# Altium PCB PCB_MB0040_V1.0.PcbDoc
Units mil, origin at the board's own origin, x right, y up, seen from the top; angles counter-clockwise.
Board outline 2760.94 x 3491.25 mil, 2 copper layers (Top Layer, Bottom Layer), stack 21 mil thick; 52 components, 72 nets, 310 pads, 64 vias.
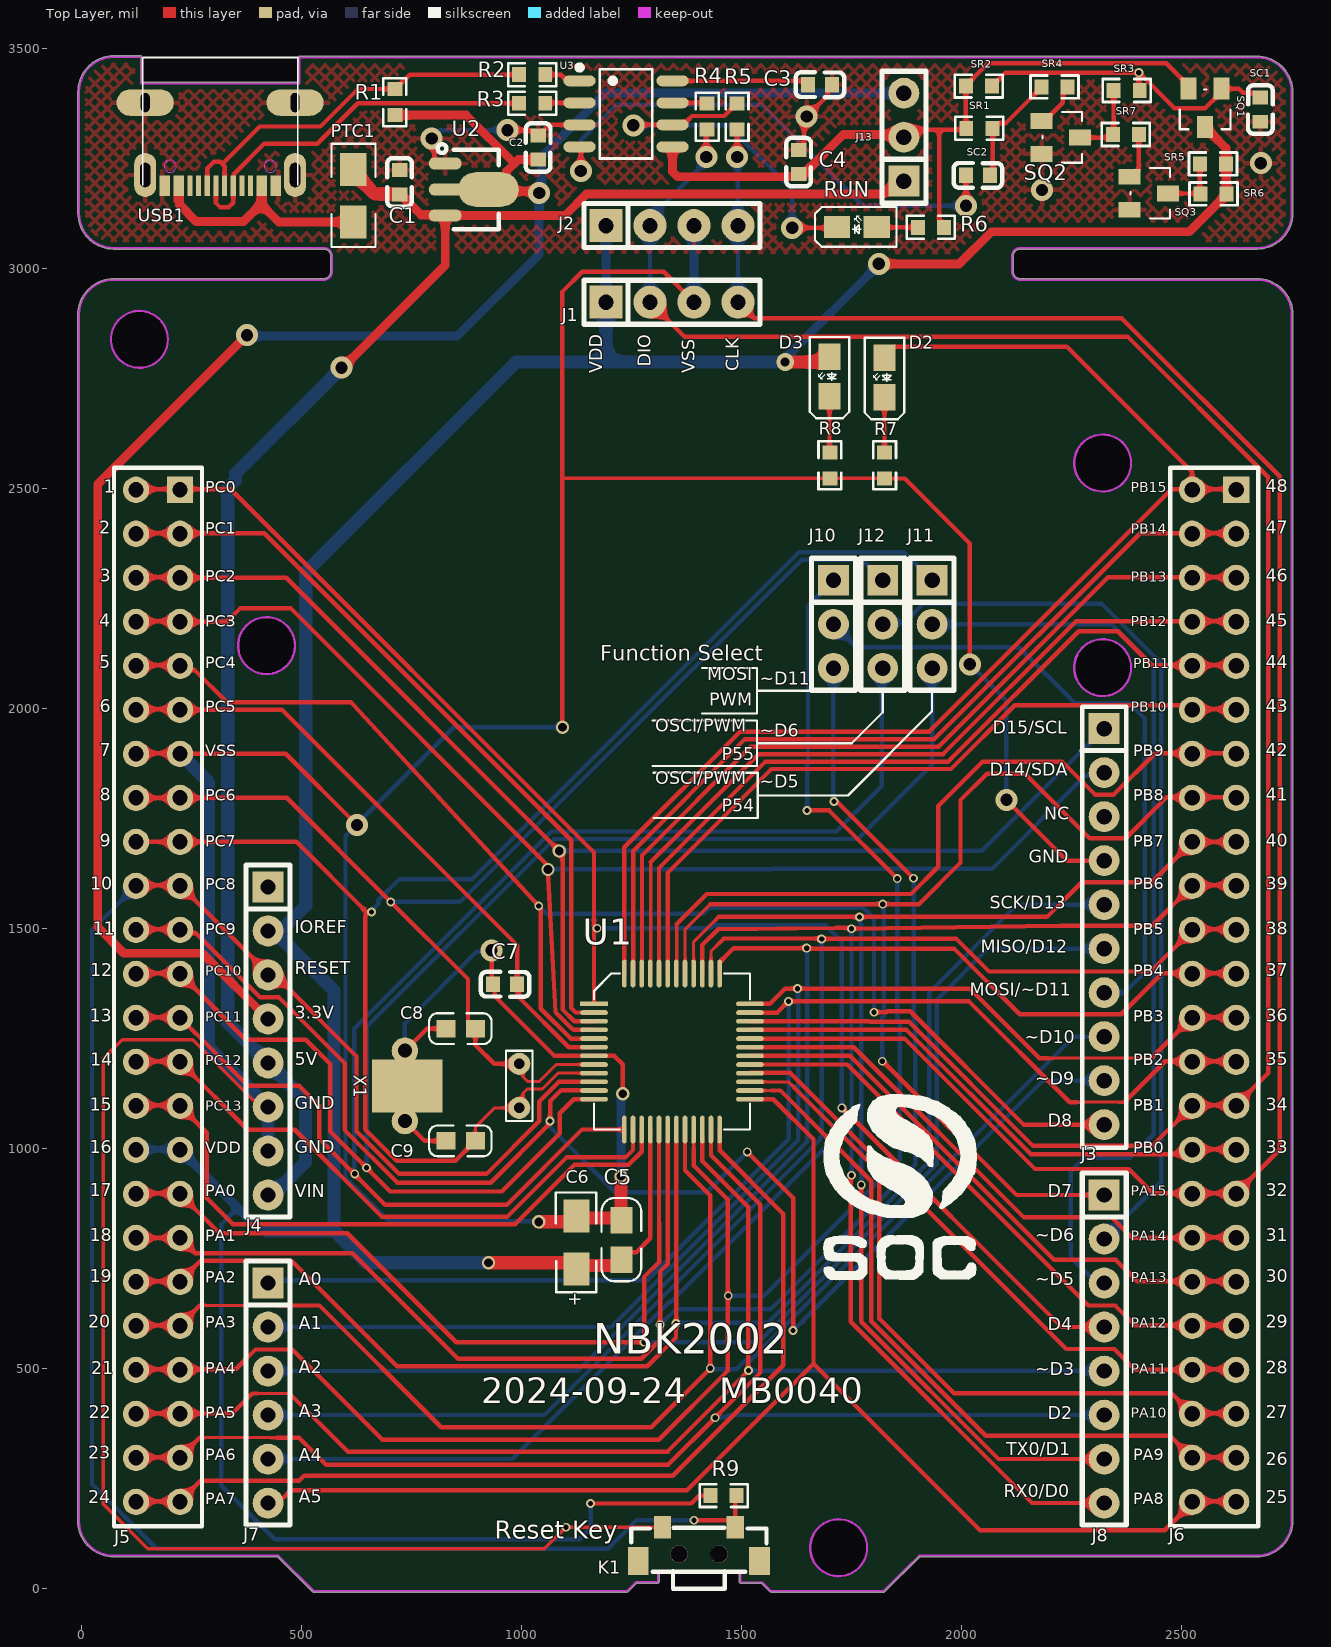
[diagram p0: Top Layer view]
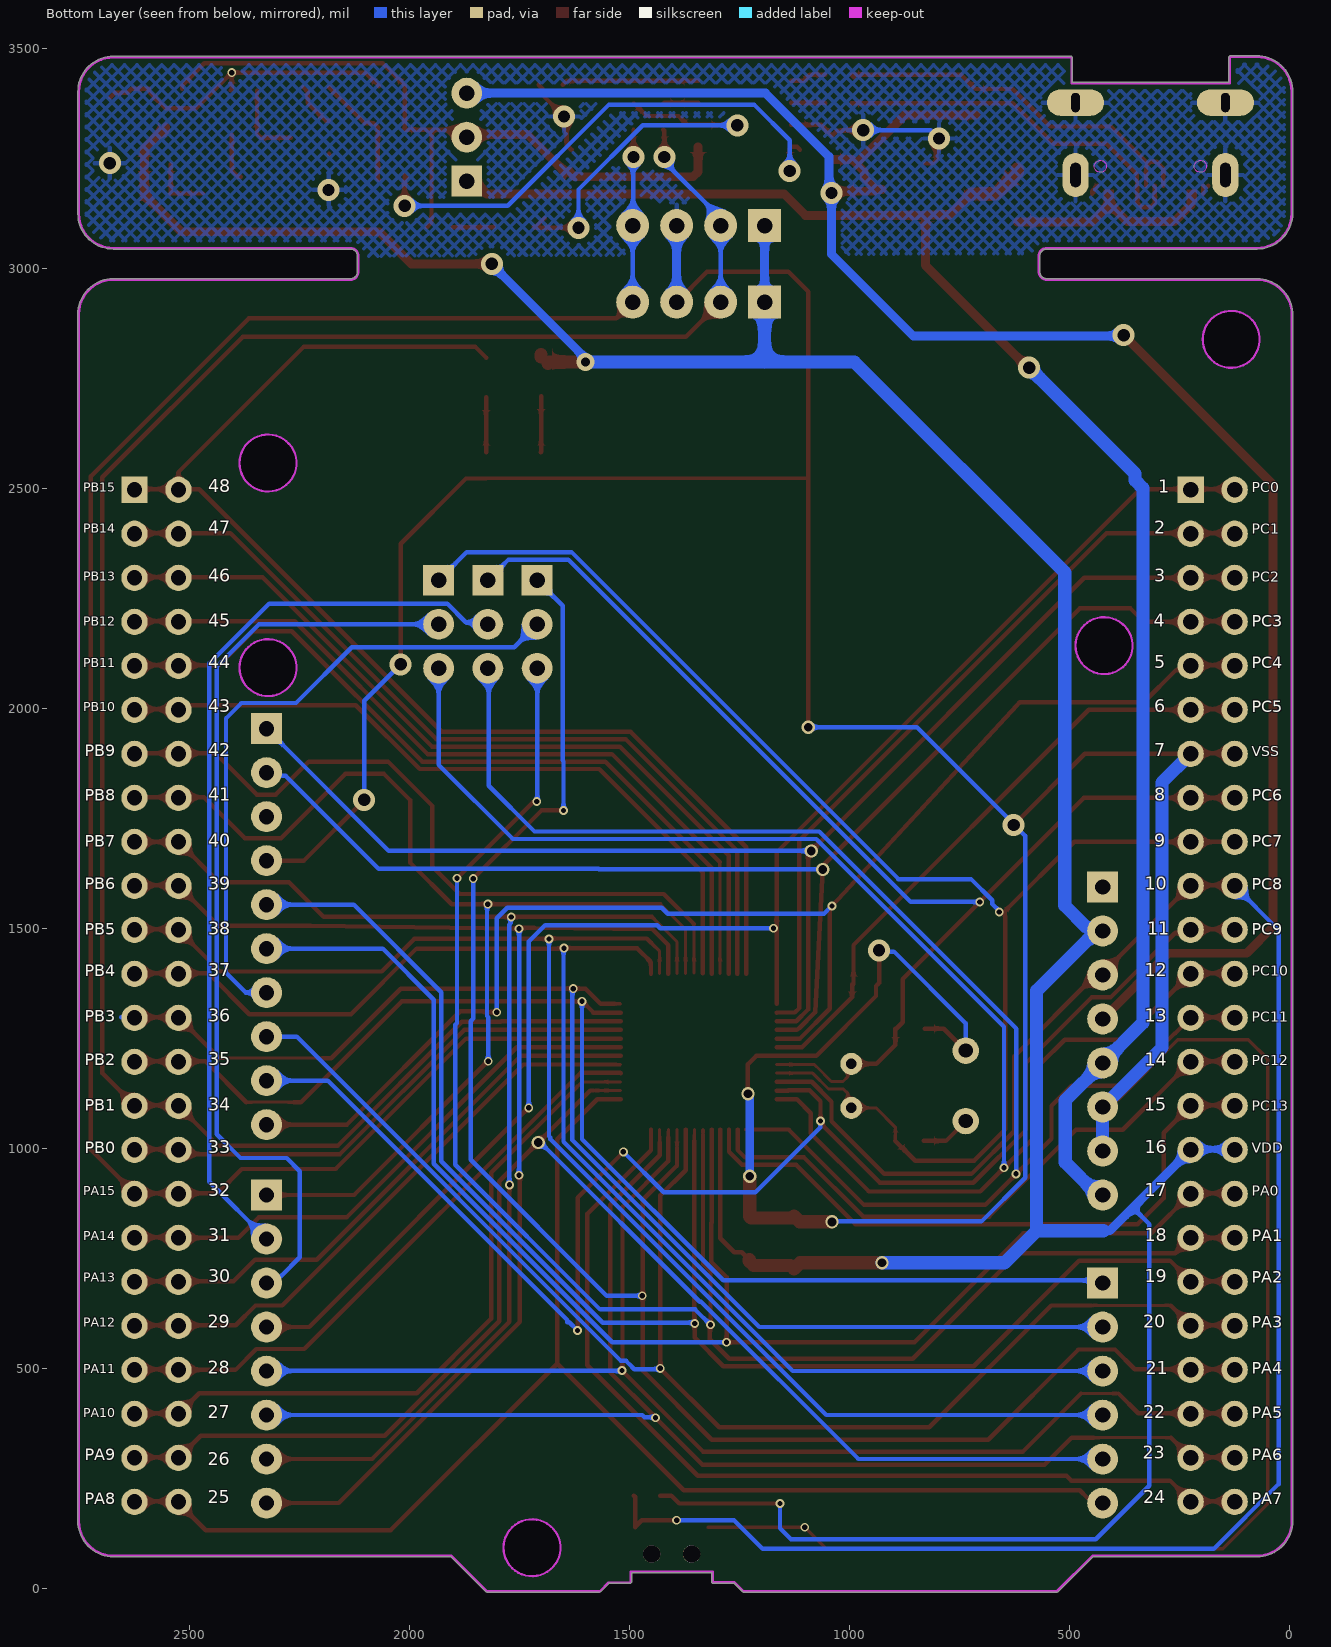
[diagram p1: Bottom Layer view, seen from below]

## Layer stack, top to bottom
Top Solder: solder mask 0.4, Solder Resist, Dk 3.5
Top Layer: signal copper 1.4
Dielectric 1: prepreg 2.8, PP-006, Dk 4.1
Dielectric1: dielectric 12.6, FR-4, Dk 4.8
Dielectric 2: prepreg 2.8, PP-006, Dk 4.1
Bottom Layer: signal copper 1.4
Bottom Solder: solder mask 0.4, Solder Resist, Dk 3.5

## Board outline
73.06,71.8 446.03,71.8 525.62,-7.79 527.39,-8.52 1240.4,-8.52 1242.18,-7.78 1261.44,11.48 1310,11.48 1312.51,14 1312.51,35.49 1494.49,35.49 1494.49,13.73 1497.36,11.21 1545.92,11.21 1565.18,-8.05 1568.1,-8.52 1823.45,-8.52 1825.23,-7.78 1904.81,71.8 2671.48,71.8 ccw(c2671.48,153.06) 2752.74,153.05 2752.74,2895.58 ccw(c2672.03,2895.58) 2672.58,2976.28 2671.95,2976.37 2133.15,2976.37 cw(c2133.15,2992) 2117.51,2992 2117.51,3028 cw(c2133.15,3028) 2133.15,3043.63 2671.95,3043.63 ccw(c2671.95,3124.34) 2752.66,3124.34 2752.66,3400.93 ccw(c2671.95,3400.93) 2671.95,3481.64 495,3481.64 492.49,3479.12 492.49,3422.52 137.51,3422.52 137.51,3480 134.78,3482.74 73.35,3482.74 ccw(c73.35,3401.48) -7.91,3401.48 -7.91,3124.89 ccw(c73.35,3124.89) 73.22,3043.63 550.95,3043.63 cw(c550.95,3028) 566.59,3028 566.59,2992 cw(c550.95,2992) 550.95,2976.37 550.06,2976.2 73.06,2976.2 ccw(c73.05,2894.94) -8.03,2900.23 -8.2,2899.31 -8.2,154 -8.2,153.05 ccw(c73.06,153.05)
cut-out: 1655.98,92.43 ccw(c1720.69,92.43) 1720.69,27.71 ccw(c1720.69,92.43) 1785.41,92.43 ccw(c1720.69,92.43) 1720.69,157.14 ccw(c1720.69,92.43)
cut-out: 2255.98,2092.43 ccw(c2320.69,2092.43) 2320.69,2027.71 ccw(c2320.69,2092.43) 2385.41,2092.43 ccw(c2320.69,2092.43) 2320.69,2157.14 ccw(c2320.69,2092.43)
cut-out: 355.98,2142.43 ccw(c420.69,2142.43) 420.69,2077.71 ccw(c420.69,2142.43) 485.41,2142.43 ccw(c420.69,2142.43) 420.69,2207.14 ccw(c420.69,2142.43)
cut-out: 2255.98,2557.43 ccw(c2320.69,2557.43) 2320.69,2492.71 ccw(c2320.69,2557.43) 2385.41,2557.43 ccw(c2320.69,2557.43) 2320.69,2622.14 ccw(c2320.69,2557.43)
cut-out: 66.98,2838.43 ccw(c131.69,2838.43) 131.69,2773.71 ccw(c131.69,2838.43) 196.41,2838.43 ccw(c131.69,2838.43) 131.69,2903.14 ccw(c131.69,2838.43)

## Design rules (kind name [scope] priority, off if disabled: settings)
Clearance [InNamedPolygon('GND_L01_P001')] p1: gap=10 ignorepadtopadclearanceinfootprint=FALSE
Clearance Clearance_2 [(InComponent('U1') AND IsPad)] p2: gap=6 ignorepadtopadclearanceinfootprint=FALSE except(0: Arc-Hole Track-Hole SMDPad-Hole THPad-Hole Via-Hole Fill-Hole Poly-Hole Region-Hole Text-Hole)
Clearance Clearance_1 [All] p3: gap=6 ignorepadtopadclearanceinfootprint=FALSE except(0: Arc-Hole Track-Hole SMDPad-Hole THPad-Hole Via-Hole Fill-Hole Poly-Hole Region-Hole Text-Hole)
ComponentClearance [All] p1 off: gap=10 collisioncheckmode=3 verticalgap=10 showdistances=FALSE
Height [All] p1 off: minheight=0 maxheight=1000 prefheight=500
HoleSize [All] p1: absolutevalues=TRUE maxlimit=150 minlimit=1 maxpercent=80.000 minpercent=20.000
MinimumSolderMaskSliver [All] p1: minsoldermaskwidth=0
PolygonConnect [All] p1: connectstyle=Relief reliefconductorwidth=10 reliefentries=4 polygonreliefangle="90 Angle" airgapwidth=10
RoutingVias [All] p1: holewidth=28 width=50 viastyle="Through Hole" minholewidth=10 minwidth=20 maxholewidth=130 maxwidth=180
SilkToSilkClearance [All] p1 off: silktosilkclearance=0
SilkToSolderMaskClearance [IsPad] p1 off: minsilkscreentomaskgap=0 clearancetoexposedcopper=TRUE
SolderMaskExpansion [All] p1: expansion=4 istentingtop=FALSE
Width [All] p1: maxlimit=30 minlimit=5 preferedwidth=7
24 further rules are at their usual default settings.

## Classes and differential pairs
component class SCH_MB0040: C1 C2 C3 C4 C5 C6 C7 C8 C9 D2 D3 J1 J2 J3 J4 J5 J6 J7 J8 J10 J11 J12 J13 K1 PTC1 R1 R2 R3 R4 R5 R6 R7 R8 R9 RUN SC1 SC2 SQ1 SQ2 SR1 SR2 SR3 SR4 SR5 SR6 SR7 U1 USB1 X1

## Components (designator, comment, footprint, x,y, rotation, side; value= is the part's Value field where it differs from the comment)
C1 "104" C0603#1 723,3195.56 r90 top
C2 "104" C0603#1 1038,3274.56 r90 top
C3 "104" C0603#1 1678.44,3417 r0 top
C4 "104" C0603#1 1630,3241.56 r90 top
C5 "104" C0805 1227,747 r90 top
C6 "10uF" A-3216 1125,726 r90 top
C7 "103" C0603#1 962.44,1373 r180 top
C8 "10pF" C0603#2 895,1272 r180 top
C9 "10pF" C0603#2 895,1017 r180 top
D2 "LED-Bule" LED0805 1825,2752 r270 top
D3 "LED-Yellow" LED0805 1700,2754 r270 top
J1 "CON1*4" CON1*4(P=2.54) 1342,2923 r0 top locked
J2 "CON1*4" CON1*4(P=2.54) 1342,3097 r0 top locked
J3 "CON1*10" CON1*10(P=2.54) 2324,1504 r270 top locked
J4 "CON1*8" CON1*8(P=2.54) 424,1244 r270 top locked
J5 "CON2*24" CON2*24(P=2.54) 189,1346.5 r270 top locked
J6 "CON2*24" CON2*24(P=2.54) 2589,1346.5 r270 top locked
J7 "CON1*6" CON1*6(P=2.54) 424,444 r270 top locked
J8 "CON1*8" CON1*8(P=2.54) 2324,544 r270 top locked
J10 "CON1*3" CON1*3(P=2.54) 1709,2191 r270 top locked
J11 "CON1*3" CON1*3(P=2.54) 1933,2191 r270 top locked
J12 "CON1*3" CON1*3(P=2.54) 1821,2191 r270 top locked
J13 "Header 4" CON1*3(P=2.54) 1869,3298 r90 top
K1 "单路开关" SW-SMD_UK-B0246-SP25Y 1403.28,100.64 r180 top
PTC1 "0.5A 6V 自恢复保险丝" R1206 618,3105 r90 top
R1 "1.5K" R0603 712,3377.66 r90 top
R2 "22R" R0603 1024.34,3440 r0 top
R3 "22R" R0603 1024.34,3375 r0 top
R4 "100R" R0603 1422,3344.66 r90 top
R5 "100R" R0603 1490,3344.66 r90 top
R6 "2.2K" R0603 1930.34,3093 r180 top
R7 "5.1K" R0603 1825,2552 r270 top
R8 "5.1K" R0603 1701,2552 r270 top
R9 "1.5K" R0603 1459.34,211 r180 top
RUN "LED-Bule" LED0805 1762,3094 r180 top (schematic designator D1)
SC1 "104" C0603#1 2679,3360.56 r270 top
SC2 "Cap" C0603#1 2037.44,3211 r0 top value=22uF
SQ1 "SI2301" sanjiguan 2516,3408 r270 top
SQ2 "SI2302" sanjiguan 2182,3260 r0 top
SQ3 "SI2302" sanjiguan 2382,3133 r0 top
SR1 "47K" R0603 2040.34,3318 r180 top
SR2 "47K" R0603 2039.34,3414 r0 top
SR3 "4.7K" R0603 2375.34,3404 r0 top
SR4 "47k" R0603 2211.34,3412 r180 top
SR5 "22R" R0603 2571.34,3237 r0 top
SR6 "22R" R0603 2572.66,3169 r0 top
SR7 "4.7K" R0603 2373.34,3304 r180 top
U1 "SC32F12TC9" CH48 1162,1045 r0 top locked
U2 "AMS1117-3.3V" AMS1117-3.3V_xiao 805.8,3119 r0 top
U3 "CH340N" CH8 1177.71,3249.57 r0 top
USB1 "TYPE-C" TYPE-C1 315.22,3282.01 r0 top locked
X1 "32.768K" 32768 995,1192 r270 top

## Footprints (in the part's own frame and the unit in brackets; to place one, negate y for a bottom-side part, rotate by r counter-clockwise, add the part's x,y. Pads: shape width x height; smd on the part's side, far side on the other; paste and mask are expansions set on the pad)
32768 [mil] "32.768KHZ"
  round 60 hole 32: 0(-30,-260) 0(130,-260)
  rect 120x160 smd: 0(50,-255)
  round 50 hole 24: 1(0,0) 2(100,0)
  silkscreen extent -30,-30 130,30
A-3216 [mil]
  rect 75x60 smd: 1(0,0) 2(120,0)
  silkscreen extent -53,-45 174,47
AMS1117-3.3V_xiao [mm]
  oval 1.9x0.7 smd paste-100 mask+0.051: 1(0.528,3.025) 3(0.528,0.023)
  oval 2.1x0.7 smd paste-100 mask+0.051: 2(0.627,1.524)
  oval 3.5x2 smd paste-100 mask+0.051: 2(3.028,1.524)
  silkscreen extent 0.09,-0.78 3.63,4.14
C0603#1 [mm]
  rect 0.8x0.9 smd paste+0 mask+0.051: 1(-0.7,0) 2(0.7,0)
  silkscreen extent -1.41,-0.71 1.39,0.72
C0603#2 [mm]
  rect 1.1x1 smd: 1(0,0) 2(1.7,0)
  silkscreen extent -0.94,-0.89 2.67,0.89
C0805 [mil]
  rect 60x50 smd: 1(0,0) 2(90,0)
  silkscreen extent -49,-45 140,45
CH8 [mm]
  oval 1.865x0.63 smd paste+0 mask+0.051: 1(-1.161,4.481) 2(-1.161,3.211) 3(-1.161,1.941) 4(-1.161,0.671) 5(4.204,0.671) 6(4.204,1.941) 7(4.204,3.211) 8(4.204,4.481)
  silkscreen extent -1.31,0 3.04,5.4
CH48 [mm]
  rect 1.6x0.27 smd: 1(0.072,7.195)
  oval 1.6x0.27 smd: 2(0.072,6.695) 3(0.072,6.195) 4(0.072,5.695) 5(0.072,5.195) 6(0.072,4.695) 7(0.072,4.195) 8(0.072,3.695) 9(0.072,3.195) 10(0.072,2.695) 11(0.072,2.195) 12(0.072,1.695) 25(9.072,1.695) 26(9.072,2.195) 27(9.072,2.695) 28(9.072,3.195) 29(9.072,3.695) 30(9.072,4.195) 31(9.072,4.695) 32(9.072,5.195) 33(9.072,5.695) 34(9.072,6.195) 35(9.072,6.695) 36(9.072,7.195)
  oval 0.27x1.6 smd: 13(1.822,-0.055) 14(2.322,-0.055) 15(2.822,-0.055) 16(3.322,-0.055) 17(3.822,-0.055) 18(4.322,-0.055) 19(4.822,-0.055) 20(5.322,-0.055) 21(5.822,-0.055) 22(6.322,-0.055) 23(6.822,-0.055) 24(7.322,-0.055) 37(7.322,8.945) 38(6.822,8.945) 39(6.322,8.945) 40(5.822,8.945) 41(5.322,8.945) 42(4.822,8.945) 43(4.322,8.945) 44(3.822,8.945) 45(3.322,8.945) 46(2.822,8.945) 47(2.322,8.945) 48(1.822,8.945)
  silkscreen extent 0.07,-0.06 9.07,8.95
CON1*3(P=2.54) [mil]
  rect 70x70 hole 35: 1(-100,0)
  round 70 hole 35: 2(0,0) 3(100,0)
  silkscreen extent -150,-50 150,50
CON1*4(P=2.54) [mil]
  rect 75x75 hole 35: 1(-150,0)
  round 75 hole 35: 2(-50,0) 3(50,0) 4(150,0)
  silkscreen extent -200,-50 200,50
CON1*6(P=2.54) [mil]
  rect 70x70 hole 35: 1(-250,0)
  round 70 hole 35: 2(-150,0) 3(-50,0) 4(50,0) 5(150,0) 6(250,0)
  silkscreen extent -300,-50 300,50
CON1*8(P=2.54) [mil]
  rect 70x70 hole 35: 1(-350,0)
  round 70 hole 35: 2(-250,0) 3(-150,0) 4(-50,0) 5(50,0) 6(150,0) 7(250,0) 8(350,0)
  silkscreen extent -400,-50 400,50
CON1*10(P=2.54) [mil]
  rect 70x70 hole 35: 1(-450,0)
  round 70 hole 35: 2(-350,0) 3(-250,0) 4(-150,0) 5(-50,0) 6(50,0) 7(150,0) 8(250,0) 9(350,0) 10(450,0)
  silkscreen extent -500,-50 502,50
CON2*24(P=2.54) [mil]
  rect 60x60 hole 35: 1(-1150,35)
  round 60 hole 35: 2(-1150,-65) 3(-1050,35) 4(-1050,-65) 5(-950,35) 6(-950,-65) 7(-850,35) 8(-850,-65) 9(-750,35) 10(-750,-65) 11(-650,35) 12(-650,-65) 13(-550,35) 14(-550,-65) 15(-450,35) 16(-450,-65) 17(-350,35) 18(-350,-65) 19(-250,35) 20(-250,-65) 21(-150,35) 22(-150,-65) 23(-50,35) 24(-50,-65) 25(50,35) 26(50,-65) 27(150,35) 28(150,-65) 29(250,35) 30(250,-65) 31(350,35) 32(350,-65) 33(450,35) 34(450,-65) 35(550,35) 36(550,-65) 37(650,35) 38(650,-65) 39(750,35) 40(750,-65) 41(850,35) 42(850,-65) 43(950,35) 44(950,-65) 45(1050,35) 46(1050,-65) 47(1150,35) 48(1150,-65)
  silkscreen extent -1200,-115 1205,85
LED0805 [mil]
  rect 60x50 smd: 1(-45,0) 2(45,0)
  silkscreen extent -90,-45 95,45
R0603 [mil]
  rect 31.75x34.02 smd paste-3937.01 mask+2: 1(-29.66,0) 2(29.66,0)
  silkscreen extent -55,-26 55,26
R1206 [mil]
  rect 75x60 smd: 1(0,0) 2(120,0)
  silkscreen extent -57,-50 178,50
sanjiguan [mil]
  rect 50x36 smd: 1(87,37) 2(0,75) 3(0,0)
  silkscreen extent 2,-20 92,95
SW-SMD_UK-B0246-SP25Y [mm]
  rect 1x1.3 smd: 1(2.1,-0.975) 2(-2.1,-0.975)
  rect 1.2x1.6 smd: 3(-3.5,0.975) 4(3.5,0.975)
  round 1 hole 1 unplated: ""(-1.15,0.575) ""(1.15,0.575)
  silkscreen extent -3.9,-0.95 3.9,2.57
TYPE-C1 [mm]
  oval 3.302x1.524 / inner oval 1.27x2.54 / far side oval 3.302x1.524 hole 0.5 slot 1.1 at 90 deg: 1(-4.325,2.4) 3(4.325,2.4)
  oval 1.27x2.54 / inner oval 1.27x2.54 / far side oval 1.524x2.54 hole 0.6 slot 1.4 at 90 deg: 2(-4.325,-1.78) 4(4.325,-1.78)
  rect 0.3x1.2 smd: A1(3.355,-2.4) A4(2.555,-2.4) A5(1.255,-2.4) A6(0.255,-2.4) A7(-0.245,-2.4) A8(-1.245,-2.4) A9(-2.545,-2.4) A12(-3.345,-2.4) B1(-3.045,-2.4) B4(-2.245,-2.4) B5(-1.745,-2.4) B6(-0.745,-2.4) B7(0.755,-2.4) B8(1.755,-2.4) B9(2.255,-2.4) B12(3.055,-2.4)
  Keep-Out Layer circle w0.05: c-2.885,-1.28 r0.35
  Keep-Out Layer circle w0.05: c2.895,-1.28 r0.35
  silkscreen extent -4.47,-2.35 4.48,5

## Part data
C1 C2 C3 C4 C5 C7 C8 C9 SC1: library part CAP1, "贴片电容"
C6: library part T-A/4.7uF/16V
D2 RUN: library part LED-CP, "蓝色"
D3: library part LED-CP, "黄色"
J13: library part "Header 3", "Header, 3-Pin"
K1: library part KEY-6
PTC1: library part PTC-MZ11-06A200-400RM, "6V 500mA PTC自恢复保险丝"
R1 R2 R3 R4 R5 R6 R7 R8 R9 SR1 SR2 SR3 SR4 SR5 SR6 SR7: library part R0805
SC2: "Capacitor"
SQ1: library part MOSFET-P, "P-Channel MOSFET"
SQ2 SQ3: library part MOSFET-N, "N-Channel MOSFET"
U1: "SC32F12TC9/48PIN"
U2: library part LDO-SPX1117M3, "LDO；1A；SOT-223-3"
USB1: library part TYPE-C1, "Type-c母座16pin 快充闪充usb3.0沉板母座连接器"
X1: library part CRYSTAL

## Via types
v1: diameter 20, hole 12, Top Layer to Bottom Layer, tented both sides, 36 vias
v2: diameter 50, hole 28, Top Layer to Bottom Layer, tented both sides, 19 vias
v3: diameter 30, hole 20, Top Layer to Bottom Layer, tented both sides, 8 vias
v4: diameter 40, hole 20, Top Layer to Bottom Layer, tented both sides, 1 vias

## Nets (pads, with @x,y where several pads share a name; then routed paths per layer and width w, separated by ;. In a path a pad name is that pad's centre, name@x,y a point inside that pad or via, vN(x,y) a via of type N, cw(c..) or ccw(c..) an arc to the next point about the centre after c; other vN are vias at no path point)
3.3V: C2.1 J4.4 J13.3 R1.1 U2.2 | length 4378.4
  Top Layer w20: v2(376,2848) 37,2509 37,1503 96.5,1443.5 274.5,1443.5 J4.4 ; R1.1 874,3348 984,3238 ; U2.2@925,3179 U2.2@938.63,3179 ; 993,3247 984,3238 ; 994,3247 C2.1 ; v2(1040,3171) 1036,3175 942.63,3175 U2.2@938.63,3179 ; U2.2@938.63,3179 965.77,3206.13 965.77,3219.77 984,3238
  Bottom Layer w20: v2(376,2848) 378,2846 854,2846 1040,3032 v2(1040,3171) 1045.74,3176.74 1045.74,3253.74 1190,3398 J13.3
5V: C1.1 J4.5 J4.8 J13.1 PTC1.2 U2.3 | length 3883.1
  Top Layer w20: v2(591,2774) 593.67,2774 826.6,3006.93 U2.3 1098.9,3119.9 1148,3169 1823,3169 J13.1@1869,3215 ; C1.1 724.97,3168 771.62,3121.35 U2.3@825.15,3121.35
  Top Layer w30: PTC1.2 618,3217.5 666.75,3168.75 722.25,3168.75 C1.1
  Bottom Layer w30: J4.8 434.82,894 509,968.18 509,1109 J4.5 332.48,1285.52 332.48,2500.38 350.05,2517.95 350.05,2533.05 v2(591,2774)
A0: J6.27 J6.28 J7.1 U1.35 | length 2886.2
  Top Layer w7: 2262,1105 2369.87,1105
  Top Layer w10: U1.35 1581.06,1308.58 1606.48,1334 2016.89,1334 2245.89,1105 2262,1105 ; 2369.87,1105 2462.87,1198 2524,1198 J6.27@2624,1198
  Bottom Layer w10: J7.1 430,700 1286,700 1607,1021 v1(1607,1334) ; J6.27@2624,1192 J6.27@2624,1198
A1: J6.25 J6.26 J7.2 U1.36 | length 2979.1
  Top Layer w7: U1.36 U1.36@1533,1328.27 ; 2197,1205 2431,1205
  Top Layer w10: U1.36@1533,1328.27 1564.27,1328.27 1599,1363 v1(1627,1363) 2019,1363 2177,1205 2197,1205 ; 2431,1205 2524,1298 J6.25@2624,1298
  Bottom Layer w10: J7.2 1204.04,594 1629,1018.96 1629,1343.11 1628.91,1343.2 1628.91,1361.09 v1(1627,1363) ; J6.25@2624,1298 2654,1298
A2: J6.23 J6.24 J7.3 U1.37 | length 3208.4
  Top Layer w10: J7.3 J7.3@433.77,484.23 ; U1.37 1450.27,1423.35 1481.92,1455 v1(1648,1455) ; v1@1648,1454 1983,1454 2132,1305 2363,1305 2456,1398 J6.23@2624,1398
  Bottom Layer w10: J7.3 1128.08,494 1649,1014.92 1649,1454 v1(1648,1455)
A3: J6.21 J6.22 J7.4 U1.38 | length 3300.3
  Top Layer w7: U1.38 1430.58,1447.58 1449.91,1466.91
  Top Layer w10: J7.4@421,394 J7.4 ; 1449.91,1466.91 1460,1477 1681,1477 v1(1682,1476) 1988.29,1476 2062.29,1402 2429.5,1402 J6.22 ; J6.22@2524,1498 J6.21@2624,1498
  Bottom Layer w10: J7.4 1052.12,394 1679.26,1021.14 1679.26,1024.7 1682,1027.44 v1(1682,1476)
A4: J6.45 J6.46 J7.5 U1.26 | length 3216.6
  Top Layer w7: U1.26 1581.58,1131.42
  Top Layer w10: 1581.58,1131.42 1588.36,1131.42 v3(1706.26,1013.51) ; v3@1710,1014.62 1710,1010.23 1795,925.23 1795,607.08 2055.08,347 2473.5,347 J6.46 ; J6.46@2524,298 J6.45@2624,298
  Bottom Layer w10: J7.5 978.89,294 1336.56,651.68 1339.68,651.68 1701.51,1013.51 v3(1706.26,1013.51)
A5: J6.47 J6.48 J7.6 U1.25 | length 3209.7
  Top Layer w10: J7.6 435.48,205.48 458.34,205.48 475.86,223 1376,223 1663.5,510.5 ; U1.25 1572.27,1111.73 1663.5,1020.5 1663.5,510.5 ; J6.47@2624,198 2524,198 2524,194 2462,132 2042,132 1663.5,510.5
CLK: J1.4 J2.4 J6.33 J6.34 R5.1 U1.32 | length 4733
  Top Layer w10: v2(1490,3253) R5.1 ; J1.4 1492.25,2923 1529.25,2886 2364.28,2886 2723,2527.28 2723,997 2624,898 2435,898 2380,953 2166.96,953 1870.43,1249.53 U1.32 ; J2.4@1492,3107 J2.4 J2.4@1506.5,3097
  Bottom Layer w10: v2(1490,3253) 1491,3252 1491,3098 J2.4 J1.4
CMOD: C7.1 J5.11 J5.12 U1.6 | length 1424.5
  Top Layer w10: J5.12@124,1998 J5.11@224,1998 ; J5.11 455.5,1996.5 990,1462 C7.1 ; C7.1@993,1373 993,1344 1107.16,1229.84 U1.6
D2: J5.45 J5.46 J8.6 U1.23 | length 3042.5
  Top Layer w7: 268.5,342.5 444.09,342.5 ; U1.23@1430.58,1013.63 U1.23
  Top Layer w10: J5.46@124,298 224,298 268.5,342.5 ; 444.09,342.5 494.5,342.5 556,281 1333.11,281 v1(1440.06,387.94) ; U1.23@1430.58,1013.63 1430.58,984.42 1543,872 1543,490.89 v1@1443.11,391
  Bottom Layer w10: J5.45@224,286 J5.45@224,298 ; v1(1440.06,387.94) 1441.11,389 1465.06,389 1470.06,394 J8.6
D4: J5.1 J5.2 J8.4 U1.1 | length 3488.3
  Top Layer w10: J5.2@124,2498 224,2498 339.23,2498 1164.83,1672.39 1164.83,1508 ; 1164.42,1507.58 1164.83,1507.16 v1@1164.83,1500.15 ; U1.1 v1@1164.83,1500.15 ; v1(1171.85,1500.15) v1@1164.83,1500.15 ; v1(1728,1092) 1729,1092 2227,594 J8.4
  Bottom Layer w10: v1(1171.85,1500.15) 1429.35,1500.15 1436.2,1507 1691,1507 1728,1470 v1(1728,1092)
D7: J6.15 J6.16 J8.1 U1.41 | length 2682.7
  Top Layer w7: U1.41@1371.8,1397.17 1371.8,1498.13 1428.67,1555
  Top Layer w10: 1428.67,1555 1903.33,1555 1997.72,1649.4 1997.72,1791.72 2057,1851 2145,1851 2291,1705 2373,1705 2466,1798 2524,1798 J6.15@2624,1798 ; v1(1820,1198) 1821,1198 2125,894 J8.1
  Bottom Layer w10: v1(1820,1198) 1820,1297.89 1823,1300.89 1823,1550.29 1821,1552.29 v1(1821,1555) ; J6.16@2524,1786 J6.16 J6.16@2524,1798
D8: J3.10 J5.9 J5.10 U1.5 | length 3179.7
  Top Layer w10: J5.10@124,2098 J5.9@224,2098 ; J5.9 233.57,2086.93 257.07,2086.93 330.5,2013.5 612.5,2013.5 618.36,2007.64 v1(1039,1550.68) ; v1@1044,1550.35 1044,1317.37 1111.85,1249.53 U1.5 ; v1(1801,1309.5) 1829,1309.5 1831,1311.5 1883.5,1311.5 2141,1054 J3.10
  Bottom Layer w10: v1(1039,1550.68) 1039.87,1550.68 1057.11,1533.44 1412.37,1533.44 1425.94,1547 1776.7,1547 1801,1522.7 v1(1801,1309.5) ; J3.10@2312,1042 J3.10
D+: R1.2 R2.1 USB1.A6 USB1.B6 | length 900.2
  Top Layer w10: USB1.B6 285.89,3226.89 301,3242 315,3242 320.13,3236.87 ; USB1.A6 325.26,3231.74 320.13,3236.87 ; R2.1@989,3434.32 R2.1 745.81,3440 713.13,3407.32 R1.2 628.32,3407.32 543.1,3322.1 405.35,3322.1 320.13,3236.87
D-: R3.1 USB1.A7 USB1.B7 | length 868.6
  Top Layer w10: USB1.A7@306.48,3186.61 USB1.A7 305.57,3148.43 315,3139 335,3139 344.94,3148.94 USB1.B7 345.85,3188.43 345.85,3213.82 415.03,3283 536,3283 628,3375 R3.1
DIO: J1.2 J2.2 J6.29 J6.30 R4.1 U1.34 | length 4732.9
  Top Layer w10: J1.2 1371,2844 2378,2844 2697,2525 2697,1171 2624,1098 J6.30@2524,1098 ; v2(1420,3252.96) 1420,3313 R4.1 ; U1.34 1790.49,1288.9 1791.89,1287.5 1880.54,1287.5 2162.54,1005.5 2433,1005.5 J6.30
  Bottom Layer w10: J1.2 J2.2 1292,3114.18 1420,3242.18 v2(1420,3252.96)
GND: C1.2 C2.2 C3.2 C4.2 C5.2 C6.2 C7.2 C8.2 C9.2 J1.3 J2.3 J3.4 J4.6 J4.7 J5.13 J5.14 K1.1 R7.2 R8.2 SC1.2 SQ2.3 SQ3.3 U1.7 U2.1 U3.3 USB1.1 USB1.2 USB1.3 USB1.4 USB1.A1 USB1.A12 USB1.B1 USB1.B12 X1.0 | length 11850.3
  Top Layer w8: J4.6 407.22,1094 390.37,1110.86 389.14,1110.86 253,1247 93,1247 49,1203 49,192 151,90 1052,90 v1(1101,139) K1.1 ; 1093,2523 1093.66,2522.34 R8.2 R7.2
  Top Layer w10: J5.14@124,1898 J5.13@224,1898 ; USB1.A12 USB1.A12@184.43,3186.61 ; USB1.B1@195.34,3169.8 USB1.B1 ; J5.13 464.5,1896.5 v2(626,1735) ; USB1.B12 447.56,3175.46 447.56,3169.55 USB1.A1@448.18,3168.9 ; X1.0@735,1062 780,1017 C9.2 C9.2@830,1017 ; X1.0@735,1222 785,1272 C8.2 ; v2(795.82,3295) 802.3,3288.53 802.3,3246.21 810.41,3238.1 U2.1 ; v2(932,1450) 932,1375.88 C7.2 938.86,1369.02 938.86,1346.14 1074.84,1210.16 U1.7 1210.84,1210.16 1230,1191 v3(1230,1124) ; v2(968,3314) 1008,3314 1009.13,3312.87 1027.25,3312.87 C2.2 1039.97,3302.12 1063.85,3326 U3.3 ; v3(1093,1957) 1093,2523 1093,2947 1138,2992 1323,2992 J1.3 ; C4.2 1631.25,3269.12 1642,3279.87 1642,3339 v2(1648,3345) 1695.66,3392.66 1695.66,3406.66 C3.2 ; R7.2 1870.66,2522.34 2019,2374 v2(2019,2100) ; v2(2102,1792) 2102,1791 2239,1654 J3.4 ; SQ2.3@2181,3259 SQ2.3
  Top Layer w30: v3(1039,833) 1112,833 C6.2 1129.5,841.5 1222.5,841.5 1226,845 v3(1226,936.5)
  Bottom Layer w8: v3(1039,833) v3@1041,835 ; v1(1101,139) v1@1101.88,139.88
  Bottom Layer w10: X1.0@735,1222 735,1284 898.22,1447.22 929.22,1447.22 v2(932,1450) ; v2(795.82,3295) 814.82,3314 v2(968,3314) ; v3(1039,833) 1038,834 699.3,834 600,933.3 600,1710 638,1748 638,1749 846,1957 v3(1093,1957) ; v2(2019,2100) 2102,2017 v2(2102,1792)
  Bottom Layer w20: v3(1226,936.5) 1226,1117.29 1230,1121.29 v3(1230,1124) ; J1.3 J2.3
  Bottom Layer w30: J5.13 289,1831.5 289,1229 J4.6 J4.7 ; USB1.4@485.5,3191.93 USB1.4
  other v2: 2183,3178 2680,3239
IOREF: C5.1 C6.1 D3.1 J1.1 J2.1 J4.2 J5.31 J5.32 R9.2 SQ1.1 SR5.2 SR6.2 U1.16 | length 8094.7
  Top Layer w10: v1(1157,193) 1386,193 1404,211 R9.2 ; C5.1 1244.14,764.14 1261.14,764.14 1292.79,795.79 U1.16
  Top Layer w20: v2(1812,3010) 1995,3010 2068,3083 2517.45,3083 2602.32,3167.87 SR6.2 2601.66,3169.66 2601.66,3236.34 SR5.2 2601,3273 2568,3306 2561,3306 2553,3314 SQ1.1
  Top Layer w30: v3(925,740) 1111,740 C6.1 1133,734 1217,734 1227,744 C5.1 ; v4(1599,2787) 1681,2787 D3.1@1684,2784 ; D3.1 D3.1@1700,2804
  Bottom Layer w10: 355.25,865.25 318,828 318,233.53 439.53,112 1132,112 1157,137 v1(1157,193) ; v4(1599,2787) v4@1599,2795.12
  Bottom Layer w15: J5.32@124,998 224,998 J5.31
  Bottom Layer w20: J5.31 355.25,865.25 407.85,812.65 422,812.65 ; J1.1 J2.1 ; v4@1599,2795.12 v2@1813.44,3009.56
  Bottom Layer w30: 422,812.65 574,812.65 ; v3(925,740) 646.65,740 574,812.65 ; J1.1 1192,2787 ; v4(1599,2787) 1192,2787 ; 574,812.65 574,1358 457.57,1474.43 454.39,1474.43 434.82,1494 J4.2 431.65,1501.65 459.65,1501.65 509.91,1551.91 509.91,2308.91 988,2787 1192,2787
MISO: J3.6 J5.33 J5.34 U1.17 | length 3428.6
  Top Layer w10: J5.34@124,898 224,898 224.75,897.25 J5.33 313.5,807 604,807 851.56,559.44 v1(1278.56,559.44) 1278.56,707.59 1313,742.03 1313,830.97 1312.47,831.5 U1.17
  Bottom Layer w10: v1(1278.56,559.44) 1538.36,559.44 1944,965.09 1944,1338 2060,1454 J3.6
MOSI: J5.35 J5.36 J10.3 U1.18 | length 3771.6
  Top Layer w7: U1.18@1332.16,1031 U1.18
  Top Layer w10: J5.36 J5.35 258.5,762 615.61,762 855.61,522 1272.23,522 1316.56,566.33 1316.56,597.44 v1(1315,599) 1315,719.99 1332.16,737.15 U1.18@1332.16,1031 ; v1(1710,1788) 1711.91,1786.09 1718.91,1786.09 v1(1891,1614)
  Bottom Layer w10: J5.35 J5.35@238.5,782 ; v1(1315,599) 1350,634 1566,634 1895,963 1895,1280.65 1891,1284.65 v1(1891,1614) ; v1@1708.5,1785.5 1708.5,2090.5 J10.3
NetC3_1: C3.1 U3.8 | length 311.4
  Top Layer w10: U3.8 1641.88,3426 C3.1
NetD1_1: R6.2 RUN.1 | length 94.1
  Top Layer w10: RUN.1 1808,3093 R6.2
NetD2_2: D2.2 R7.1 | length 125.3
  Top Layer w10: R7.1 D2.2
NetD3_2: D3.2 R8.1 | length 127.8
  Top Layer w10: D3.2 1700,2582.66 R8.1
NetSC1_1: SC1.1 SQ1.2 SR2.2 SR3.2 | length 735.3
  Top Layer w10: SR2.2 2069,3415.13 2079.88,3426.01 2081.01,3426.01 2099.62,3444.62 2398.38,3444.62 2403,3449.24 v1(2403,3444.62) ; SR3.2 2403,3406 v1(2403,3444.62) ; SC1.1 2668.25,3398.87 2639.71,3398.87 2630.58,3408 SQ1.2 2591,3401 2554,3364 2483.62,3364 v1(2403,3444.62)
NetSC2_2: SC2.2 SR1.1 SR4.2 | length 271.1
  Top Layer w10: SC2.2@2069.12,3201 2071,3202.88 SR1.1@2071,3318 ; SR1.1@2071,3319 SR1.1 2070,3319.13 2080.88,3330.01 2100.82,3330.01 2181.68,3410.87 SR4.2
NetSQ2_1: SQ2.1 SR3.1 SR7.2 | length 178.4
  Top Layer w10: SQ2.1 2336.68,3297 SR7.2 2345.68,3306 SR3.1
NetSQ2_2: SQ2.2 SR4.1 | length 105.5
  Top Layer w10: SQ2.2 2189,3335 2230.12,3376.12 2230.12,3401.12 SR4.1
NetSQ3_1: SQ3.1 SR5.1 SR6.1 | length 141.5
  Top Layer w10: SQ3.1 SR6.1@2542,3170 ; SR5.1 2541.68,3170.32 SR6.1@2542,3170 ; SR6.1 SR6.1@2542,3170
NetSQ3_2: SQ3.2 SR7.1 | length 108.8
  Top Layer w10: SQ3.2 2389,3208 2403,3222 SR7.1
PA7: J5.47 J5.48 U1.24 | length 2194.8
  Top Layer w10: J5.48@124,198 224,198 271,245 495,245 506,256 1344,256 1595,507 1595,851 1450.27,995.73 U1.24
PA10: J6.43 J6.44 U1.27 | length 1611.8
  Top Layer w7: U1.27 1606.86,1151.1 1618.38,1139.58
  Top Layer w10: 1618.38,1139.58 1813,944.96 1813,613.12 1982.59,443.53 2476.97,443.53 J6.44 ; J6.44@2524,398 J6.43@2624,398
PA11: J6.41 J6.42 U1.28 | length 1384.7
  Top Layer w10: U1.28 1519.85,1171.47 1610.53,1171.47 2238,544 2347.13,544 2394.63,496.5 J6.42 ; J6.42@2524,498 J6.41@2624,498
PA12: J6.39 J6.40 U1.29 | length 1350.2
  Top Layer w7: U1.29 U1.29@1531,1190.47
  Top Layer w10: U1.29@1531,1190.47 1740.53,1190.47 2288,643 2349,643 2394,598 J6.39@2624,598
PA13: J6.37 J6.38 U1.30 | length 1317
  Top Layer w10: U1.30 1746.84,1210.16 2210,747 2350,747 2399,698 2524,698 J6.37@2624,698
PA14: J6.35 J6.36 U1.31 | length 1284.3
  Top Layer w10: U1.31 1755.16,1229.84 2142,843 2341.47,843 2387.97,796.5 J6.36 ; J6.36@2524,798 J6.35@2624,798
PB0: J6.31 J6.32 U1.33 | length 1225.7
  Top Layer w10: U1.33 1874.79,1269.21 2157,987 2514.5,987 J6.32 ; J6.32@2524,998 J6.31@2624,998
PB9: J6.13 J6.14 U1.42 | length 1686.6
  Top Layer w7: U1.42@1352.8,1398.17 1352.8,1509.8
  Top Layer w10: 1352.8,1509.8 1421,1578 1885,1578 1947,1640 1947,1778 2048,1879 2228.29,1879 2303.29,1804 2346,1804 2440,1898 2524,1898 J6.13@2624,1898
PB10: J6.11 J6.12 U1.43 | length 1681
  Top Layer w10: U1.43@1332.8,1398.17 1332.8,1626.8 1568,1862 1976,1862 2121,2007 2515,2007 2524,1998 J6.11@2624,1998
PB11: J6.9 J6.10 U1.44 | length 1806.5
  Top Layer w10: U1.44 1312.47,1637.1 1554.37,1879 1970,1879 2266.35,2175.35 2355.04,2175.35 2432.39,2098 2524,2098 J6.9@2624,2098
PB12: J6.7 J6.8 U1.45 | length 1810.5
  Top Layer w7: U1.45@1293.8,1397.17 1293.8,1650.8
  Top Layer w10: 1293.8,1650.8 1539,1896 1958,1896 2260,2198 2524,2198 J6.7@2624,2198
PB13: J6.5 J6.6 U1.46 | length 1880.7
  Top Layer w10: U1.46@1273.8,1397.17 1273.8,1665.8 1521,1913 1948,1913 2333,2298 2524,2298 J6.5@2624,2298
PB14: J6.3 J6.4 U1.47 | length 1948
  Top Layer w10: U1.47@1253.73,1397.17 1253.8,1397.23 1253.8,1675.8 1508,1930 1938,1930 2406,2398 2524,2398 J6.3@2624,2398
PB15: D2.1 J6.1 J6.2 U1.48 | length 2882.2
  Top Layer w10: U1.48 1233.73,1684.02 1496.72,1947 1926,1947 2477,2498 J6.2@2524,2498 ; D2.1 1850,2822 2239,2822 2524,2537 J6.2@2524,2498 ; J6.2 J6.2@2524,2498 ; J6.1@2624,2498 J6.2@2524,2498
PC1: J5.3 J5.4 U1.2 | length 1715.4
  Top Layer w10: J5.4@124,2398 224,2398 415.18,2398 1113,1700.18 1113,1319 1123.3,1308.7 1164.71,1308.7 U1.2
PC10: J5.23 J5.24 J11.3 U1.12 | length 3672.2
  Top Layer w10: J5.24@124,1398 224,1398 331.5,1290.5 ; J5.23 373.5,1247 510,1247 565,1192 565,1039 v1(648,956) 702,902 955.1,902 1087,1033.9 1087,1080 1118.73,1111.73 U1.12
  Bottom Layer w10: v1(648,956) 648,1276.18 1074.82,1703 1764,1703 1933,1872 J11.3
PC11: J5.25 J5.26 J12.3 U1.13 | length 3427.7
  Top Layer w10: J5.26@124,1298 J5.25@224,1298 ; J5.25 258.5,1262 259.21,1262 378.71,1142.5 494.5,1142.5 540,1097 540,1022 v1@620,942 ; v1(621,942) v1@620,942 ; U1.13 1137.55,1042.83 966.22,871.5 690.5,871.5 v1@620,942
  Bottom Layer w10: v1(621,942) 620,943 620,1272.23 1067.77,1720 1715,1720 1819,1824 1819,2089 J12.3
PC12: J5.27 J5.28 U1.14 | length 1410
  Top Layer w7: 1236.38,978 1237,978 1253.42,994.42 1253.42,996.54
  Top Layer w10: J5.28@124,1198 J5.27@224,1198 ; J5.27 378,1042.5 484.5,1042.5 682,845 968,845 1102.5,979.5 1236.38,979.5 1253.42,996.54 U1.14
PC13: J5.29 J5.30 U1.15 | length 1466
  Top Layer w10: J5.30@124,1098 J5.29@224,1098 ; J5.29 285,1035.5 285,887 344,828 986,828 1120.5,962.5 1243.42,962.5 1273.1,992.18 U1.15
PWM/OSCI: C8.1 J5.15 J5.16 J12.1 U1.8 X1.1 | length 2874.8
  Top Layer w7: X1.1 1003.23,1183.77 1003.23,1162.77 1014,1152 1040.4,1152 1073.19,1184.79 1073.3,1184.79 1078.99,1190.47 U1.8
  Top Layer w10: J5.16 466.5,1796.5 v1(703,1560) 878.35,1384.65 878.35,1286.69 893.03,1272 C8.1 895,1235 938,1192 X1.1
  Bottom Layer w10: v1(703,1560) 860.04,1560 1638.04,2338 1774,2338 J12.1
PWM/OSCO: C9.1 J5.17 J5.18 J11.1 U1.9 X1.2 | length 3462.8
  Top Layer w7: C9.1 895,1048 939,1092 X1.2 1003.23,1100.23 1003.23,1125.23 1013,1135 1047.04,1135 ; 1079.83,1167.79 1047.04,1135 ; U1.9 1082.83,1170.79 1047.04,1135
  Top Layer w10: J5.18 J5.17 488.5,1696.5 648,1537 ; v1(659,1537) 648,1537 ; C9.1 850,972 716.08,972 645,1043.08 645,1526.93 646.09,1528.02 646.09,1535.09 648,1537
  Bottom Layer w7: X1.2 X1.2@1005,1092
  Bottom Layer w10: v1(659,1537) 659,1539.71 674.71,1555.42 674.71,1563.71 723,1612 888,1612 1631,2355 1869,2355 J11.1
RESET: J4.3 J5.19 J5.20 K1.2 R9.1 U1.10 | length 4558.3
  Top Layer w10: J5.20@124,1598 224,1598 424,1398 J4.3 427,1391 443,1391 625,1209 625,1039.04 722.04,942 920.39,942 1040,1061.61 1040,1106.04 1085.06,1151.1 U1.10 ; v1(1392,155) 1471.27,155 1485.96,140.32 K1.2 1485.96,207.96 R9.1
  Bottom Layer w10: J5.20 24,1496.5 24,237.1 171.1,90 1196.61,90 1261.61,155 v1(1392,155)
RTS: SC2.1 U3.4 | length 1229.2
  Top Layer w10: U3.4@1111.69,3269.16 1118.52,3276 U3.4 1135,3273 v2(1135,3221) ; SC2.1@2005,3206.12 SC2.1 2010,3210.88 v2(2010,3142)
  Bottom Layer w10: v2(1135,3221) 1135,3291 1216,3372 1545.63,3372 1775.63,3142 v2(2010,3142)
RX: R4.2 U3.7 | length 79.5
  Top Layer w10: U3.7 1420.32,3376 R4.2
RXD4: J6.19 J6.20 J8.8 U1.39 | length 2973.9
  Top Layer w10: U1.39 1410.9,1461.9 1447.07,1498.07 1715,1500.88 1715.12,1501 1730,1501 1730.09,1500.91 1748.09,1500.91 v1(1750,1499) ; v1(1750,939.06) 1748.09,937.14 1748.09,605.91 2160,194 J8.8 ; v1@1750,1499.07 2224.03,1505.61 2433.11,1505.61 2522.36,1594.86 J6.20 ; J6.20@2524,1598 2622.5,1598 J6.19
  Bottom Layer w10: v1(1750,939.06) v1(1750,1499) ; J6.19 J6.19@2625.5,1596.5
SCK: J3.5 J5.37 J5.38 U1.19 | length 3442.3
  Top Layer w7: U1.19@1351.84,1017.17 U1.19
  Top Layer w10: J5.38@124,698 224,698 271,745 477,745 717,505 1286,505 1351,570 v1(1351,602) 1351.84,602.84 U1.19@1351.84,1017.17
  Bottom Layer w10: J5.37@224,698 J5.37@228,698 ; v1(1351,602) 1352.91,603.91 1559.95,603.91 1927,970.96 1927,1355 2126,1554 J3.5
SCL: J3.1 J5.5 J5.6 U1.3 | length 3015.7
  Top Layer w10: J5.6@124,2298 224,2298 225.5,2296.5 465.5,2296.5 v3(1086,1676) ; v3@1093.33,1676 1093.33,1315.67 1119.98,1289.02 1138.09,1289.02 1164.71,1289.02 U1.3
  Bottom Layer w10: v3(1086,1676) 2046,1676 J3.1
SDA: J3.2 J5.7 J5.8 U1.4 | length 2983.5
  Top Layer w10: J5.8@124,2198 J5.7@224,2198 ; J5.7 330,2196.5 360.5,2227 476,2227 481.86,2221.14 1060,1642.28 v3(1060,1634) 1077.33,1309.05 1113.35,1273.02 1118.81,1269.33 1164.71,1269.33 U1.4
  Bottom Layer w10: v3(1060,1634) 1568.62,1634 1569.62,1635 2069,1635 2280.64,1846.64 2316.64,1846.64 J3.2
TX: R5.2 RUN.2 U3.6 | length 901.1
  Top Layer w10: v2(1254,3325) 1255.22,3326.22 1291.29,3326.22 1291.51,3326 U3.6 1367.53,3326 1387.67,3346.14 1460.69,3346.14 1488.87,3374.32 R5.2 ; v2(1615,3092) 1715,3092 RUN.2 1712,3094 RUN.2@1692,3114
  Bottom Layer w10: v2(1254,3325) 1468.91,3325 1615,3178.91 v2(1615,3092)
TXD4: J6.17 J6.18 J8.7 U1.40 | length 3001.8
  Top Layer w7: U1.40 1391.21,1469.21 1448,1526
  Top Layer w10: 1448,1526 v1(1768,1526) 2194,1526 2273,1605 2432.5,1605 J6.18 J6.17 ; v1(1772,917) 1772,606.04 2084.04,294 J8.7
  Bottom Layer w10: v1(1768,1526) 1769.91,1524.09 1769.91,1510.2 1772,1508.11 v1(1772,917)
USB_D+: R2.2 U3.1 | length 83.8
  Top Layer w10: R2.2 1089.68,3440 1103.68,3426 U3.1
USB_D-: R3.2 U3.2 | length 78.4
  Top Layer w10: R3.2 1055,3376 U3.2
VCC: C4.1 J13.2 R6.1 SQ1.3 SR1.2 SR2.1 U3.5 | length 1651.3
  Top Layer w10: J13.2@1869,3315 1949.12,3315 ; R6.1 1949.12,3103.88 1949.12,3315 ; SQ1.3 2516,3415 2465.38,3465.62 2060.17,3465.62 2009.68,3415.13 SR2.1 2009.68,3319 SR1.2 2007.68,3315 1949.12,3315
  Top Layer w20: U3.5 1343.22,3219.72 1354.94,3208 1610.57,3208 1610.82,3208.25 1624.25,3208.25 1635.75,3219.75 1646.75,3219.75 1731,3304 1863,3304 J13.2
VIN: PTC1.1 USB1.A4 USB1.A9 USB1.B4 USB1.B9 | length 484.9
  Top Layer w20: USB1.B4@221,3164.5 223,3162.5 223,3144 261,3106 368,3106 408,3146 ; USB1.A4@410,3164.5 408,3162.5 408,3146 ; PTC1.1 449,3105 408,3146
~D3: J5.43 J5.44 J8.5 U1.22 | length 2962.3
  Top Layer w7: 388,443 473,443 ; U1.22@1410.9,1024.9 U1.22
  Top Layer w10: J5.44@124,398 343,398 388,443 ; 473,443 605,311 1332,311 v1(1516,495) 1515,496 1515,867 1410.9,971.1 U1.22@1410.9,1024.9 ; J8.5@2303,494 J8.5
  Bottom Layer w10: v1(1516,495) 1516.5,494.5 2323.5,494.5 J8.5
~D5: J8.3 J11.2 | length 2140
  Top Layer w10: J8.3 J8.3@2338,694
  Bottom Layer w10: J11.2 2340.96,2191 2437,2094.96 2437,1032 2383,978 2278,978 2248.19,948.19 2248.19,752.53 2290,710.71 2291.05,710.71 2307.76,694 J8.3
~D6: J8.2 J12.2 | length 2101.6
  Top Layer w10: J8.2@2293,794 J8.2
  Bottom Layer w10: J12.2 1825.47,2195.47 1871,2195.47 1913.53,2238 2318,2238 2454,2102 2454,924 J8.2
~D9: J3.9 J5.21 J5.22 U1.11 | length 3441.3
  Top Layer w10: J5.22@124,1498 224,1498 J5.21@224,1496.61 ; J5.21 231.51,1488.99 260.13,1488.99 406.11,1343 449,1343 598,1194 598,1042 718,922 930,922 1065,1057 v1(1065,1062) 1065,1107 1090,1132 1137.98,1132 1138.88,1131.1 1164.52,1131.1 U1.11 ; v1(1513,992) 1617.12,887.88 v1(1617.12,585.88)
  Bottom Layer w10: v1(1065,1062) 1065.68,1061.32 1065.68,1047.32 1213,900 1421,900 v1(1513,992) ; v1(1617.12,585.88) 1636.22,604.98 1640.21,604.98 1640.21,609.21 2185,1154 J3.9
~D10: J3.8 J5.39 J5.40 U1.20 | length 3269.8
  Top Layer w7: 269,643 450,643
  Top Layer w10: J5.40@124,598 224,598 269,643 ; 450,643 540.72,643 817.72,366 1295,366 v1(1429,500) 1429,893 1371.53,950.47 U1.20
  Bottom Layer w10: v1(1429,500) 1430.91,498.09 1451.75,498.09 1451.92,497.92 1488.14,497.92 1494,503.77 1494,504.11 1506.89,517 1518.54,517 2255.54,1254 J3.8
~D11: J5.41 J5.42 J10.1 U1.21 | length 4070.2
  Top Layer w7: 1391.21,1001.81 U1.21
  Top Layer w10: J5.42@124,498 350.7,498 395.7,543 479,543 684,338 1312,338 1469,495 1469,665 1469,883 1391.21,960.79 1391.21,1001.81 ; v1(1649,1768) 1699,1768 v1(1854,1613)
  Bottom Layer w10: v1(1470,665) 1551.11,665 1860,973.89 1860,1289.09 1854,1295.09 v1(1854,1613) ; v1(1649,1768) 1649,1880.03 1651,1882.03 1651,2233 J10.1
~D11/MOSI: J3.7 J10.2 | length 1484.3
  Bottom Layer w10: J10.2 1761,2139 2130,2139 2257,2012 2381,2012 2416,1977 2416,1399 2371,1354 J3.7
pads on no net: J3.3 J4.1 K1. K1.3 K1.4 USB1.A5 USB1.A8 USB1.B5 USB1.B8

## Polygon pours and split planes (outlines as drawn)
GND on Top Layer "GND_L01_P001" (hatched 45Degree grid 20 track 8, remove dead copper, pour order 2): -11,3038 -7,3042 -7,3492 2855,3492 2855,3034
GND on Bottom Layer "GND_L01_P001" (hatched 45Degree grid 20 track 8, remove dead copper, pour order 6): -16,3036 -16,3502 -11,3507 -9,3505 2807,3505 2807,3040 2792,3025

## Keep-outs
Keep-Out Layer:
  circle w5: c1720.69,92.43 r64.72
  circle w5: c1720.69,92.43 r64.72
  circle w5: c420.69,2142.43 r64.72
  circle w5: c2320.69,2092.43 r64.72
  circle w5: c131.69,2838.43 r64.72
  circle w5: c2320.69,2557.43 r64.72
  lines w5: -5.68,153.05 ccw(c73.06,153.05) 73.06,74.31 447.07,74.31 527.39,-6 1240.4,-6 1260.4,14 1310,14 1310,38 1343,38 1464,38 ; -5.69,154 -5.69,2899.31 ; -5.69,2894.94 cw(c73.06,2894.94) 73.06,2973.69 550.79,2973.69 ; 73.22,3046.15 550.95,3046.15 cw(c550.95,3028) 569.1,3028 569.1,2992 cw(c550.95,2992) 550.95,2973.85 ; 73.35,3046.15 cw(c73.35,3124.89) -5.39,3124.89 -5.39,3401.48 cw(c73.35,3401.48) 73.35,3480.22 134.78,3480.22 135,3480 135,3420 495,3420 495,3479.12 2671.95,3479.12 cw(c2671.95,3400.93) 2750.14,3400.93 2750.14,3124.34 cw(c2671.95,3124.34) 2671.95,3046.15 2133.15,3046.15 ccw(c2133.15,3028) 2115,3028 2115,2992 ccw(c2133.15,2992) 2133.15,2973.85 2671.95,2973.85 ; 1344,38 1464,38 ; 1497,13.73 1497,38 1464,38 ; 1497.36,13.73 1546.96,13.73 1566.96,-6.27 ; 1566.96,-6 1823.45,-6 ; 1825.02,-4.43 1868.45,39 ; 1888.45,59 1823.45,-6 ; 2672.03,2973.77 cw(c2672.03,2895.58) 2750.22,2895.58 2750.22,153.05 cw(c2671.48,153.06) 2671.48,74.31 1903.76,74.31 1823.45,-6

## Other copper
Top Layer:
  rectangle net VIN: 398,3150 422,3179
  rectangle net VIN: 209,3150 233,3179
  pour cut-out: 1289.5,141 1512.5,141 1512.5,27 1511.5,28 1290.5,28
Bottom Layer:
  pour cut-out: 1290.5,140 1513.5,140 1513.5,26 1512.5,27 1291.5,27

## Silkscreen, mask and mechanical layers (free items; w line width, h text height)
Top Overlay:
  drawing of 21 lines, arcs and shapes, not listed
  text "DIO" at 1304.02,2776 h50 r90
  text "CLK" at 1504.02,2766 h50 r90
  text "VDD" at 1194,2760.95 h50 r90
  text "VSS" at 1404.02,2760.95 h50 r90
  text "PB15" at 2385,2483.4 h40
  text "PC0" at 281,2481.33 h46
  text "1" at 50.42,2480 h50
  text "48" at 2691.06,2480.27 h50
  text "PB14" at 2385,2389.19 h40
  text "PC1" at 281,2387.33 h46
  text "2" at 40.96,2386 h50
  text "47" at 2691.06,2386.06 h50
  text "PB13" at 2385,2280.13 h40
  text "PC2" at 281,2278.05 h46
  text "3" at 41.27,2276.99 h50
  text "46" at 2691.06,2276.99 h50
  text "PB12" at 2385,2178.12 h40
  text "PC3" at 281,2176.26 h46
  text "4" at 40.02,2175 h50
  text "45" at 2691.06,2175.26 h50
  text "Function Select" at 1179,2096.05 h60
  text "PB11" at 2390,2083.64 h40
  text "PC4" at 281,2081.78 h46
  text "5" at 40.99,2080.98 h50
  text "44" at 2691.06,2080.51 h50
  text "MOSI" at 1422.01,2052.99 h50
  text "~D11" at 1541,2042.95 h50
  text "PWM" at 1426.54,1996.01 h50
  text "PB10" at 2385,1983.85 h40
  text "PC5" at 281,1981.78 h46
  text "6" at 41.04,1980.71 h50
  text "43" at 2691.06,1980.71 h50
  text "OSCI/PWM" at 1303.6,1935.99 h50
  text "D15/SCL" at 2070.86,1931.98 h50
  text "~D6" at 1541,1925.21 h50
  text "VSS" at 281,1881.78 h46
  text "PB9" at 2390,1881.98 h46
  text "7" at 41.5,1880.71 h50
  text "42" at 2691.06,1880.45 h50
  text "P55" at 1454.63,1872.28 h50
  text "D14/SDA" at 2064.27,1836.98 h50
  text "OSCI/PWM" at 1303.6,1816.99 h50
  text "~D5" at 1541,1809.28 h50
  text "PC6" at 281,1781.05 h46
  text "PB8" at 2390,1781.26 h46
  text "8" at 41.13,1779.99 h50
  text "41" at 2691.06,1779.72 h50
  text "P54" at 1455,1755.28 h50
  text "NC" at 2187.93,1736.98 h50
  text "PC7" at 281,1676.05 h46
  text "PB7" at 2390,1676.07 h46
  text "9" at 41.18,1674.99 h50
  text "40" at 2691.06,1674.99 h50
  text "GND" at 2152.74,1638.98 h50
  text "PC8" at 281,1579.05 h46
  text "PB6" at 2390,1579.26 h46
  text "10" at 19.46,1577.99 h50
  text "39" at 2691.06,1577.99 h50
  text "SCK/D13" at 2064.36,1533.98 h50
  text "IOREF" at 485,1478.98 h50
  text "PB5" at 2390,1476.59 h46
  text "PC9" at 281,1476.33 h46
  text "11" at 25.56,1475 h50
  text "38" at 2691.06,1475.27 h50
  text "MISO/D12" at 2043.92,1433.98 h50
  text "RESET" at 485,1384.98 h50
  text "PC10" at 281,1384.18 h40
  text "PB4" at 2390,1382.35 h46
  text "12" at 19.69,1381 h50
  text "37" at 2691.06,1381.27 h50
  text "MOSI/~D11" at 2018.2,1336.98 h50
  text "3.3V" at 485,1283.99 h50
  text "PC11" at 281,1279.95 h40
  text "PB3" at 2390,1278.26 h46
  text "13" at 19.37,1276.99 h50
  text "36" at 2691.06,1276.99 h50
  text "~D10" at 2143.18,1228.99 h50
  text "PC12" at 281,1181.23 h40
  text "5V" at 485,1178.98 h50
  text "PB2" at 2390,1179.29 h46
  text "14" at 19.51,1178 h50
  text "35" at 2691.06,1178.27 h50
  text "~D9" at 2167.87,1133.99 h50
  text "GND" at 485,1078.98 h50
  text "PC13" at 281,1077.95 h40
  text "PB1" at 2390,1076.01 h46
  text "15" at 19.14,1074.99 h50
  text "34" at 2691.06,1074.99 h50
  text "D8" at 2195.59,1038.99 h50
  text "VDD" at 281,980.07 h46
  text "PB0" at 2390,980.26 h46
  text "16" at 19.37,978.99 h50
  text "GND" at 485,978.98 h50
  text "33" at 2691.06,978.99 h50
  text "PA15" at 2385,884.4 h40
  text "PA0" at 281,882.53 h46
  text "17" at 19.37,881 h50
  text "32" at 2691.06,881.27 h50
  text "VIN" at 485.01,879 h50
  text "D7" at 2195.69,879 h50
  text "PA14" at 2385,781.91 h40
  text "PA1" at 281,780.01 h46
  text "18" at 19.33,778.99 h50
  text "~D6" at 2167.97,778.99 h50
  text "31" at 2691.06,778.99 h50
  text "PA13" at 2385,688.13 h40
  text "PA2" at 281,686.01 h46
  text "19" at 19.33,684.99 h50
  text "30" at 2691.06,684.99 h50
  text "A0" at 493.97,678.99 h50
  text "~D5" at 2167.72,678.98 h50
  text "PA12" at 2385,584.91 h40
  text "PA3" at 281,583.26 h46
  text "20" at 15.88,581.99 h50
  text "29" at 2691.01,581.99 h50
  text "A1" at 493.97,579 h50
  text "D4" at 2195.78,577 h50
  text "NBK2002" at 1163,509.94 h120
  text "PA11" at 2385,480.19 h40
  text "A2" at 493.97,479 h50
  text "PA4" at 281,478.35 h46
  text "21" at 21.97,477 h50
  text "28" at 2691.01,477.27 h50
  text "~D3" at 2167.97,473.99 h50
  text "2024-09-24   MB0040" at 908.8,401 h100
  text "A3" at 493.97,378.99 h50
  text "PA10" at 2385,379.4 h40
  text "PA5" at 281,377.59 h46
  text "22" at 16.11,376 h50
  text "27" at 2691.01,376 h50
  text "D2" at 2195.98,374 h50
  text "TX0/D1" at 2101.26,291.98 h50
  text "23" at 15.78,283.99 h50
  text "PA6" at 281,281.98 h46
  text "PA9" at 2390,281.98 h46
  text "A4" at 493.97,279 h50
  text "26" at 2691.01,269.99 h50
  text "RX0/D0" at 2096.28,196.98 h50
  text "A5" at 493.97,183.98 h50
  text "24" at 15.92,183 h50
  text "25" at 2691.01,183.27 h50
  text "PA7" at 281,181.79 h46
  text "PA8" at 2390,181.98 h46
  text "Reset Key" at 939,99.2 h70
Bottom Overlay:
  text "PB15" at 2740,2484.67 h36
  text "PC0" at 85,2483.23 h40
  text "1" at 297.58,2480 h50
  text "48" at 2456.94,2480.27 h50
  text "PB14" at 2740,2390.48 h36
  text "PC1" at 85,2389.23 h40
  text "2" at 307.04,2386 h50
  text "47" at 2456.94,2386.06 h50
  text "PB13" at 2740,2281.39 h36
  text "PC2" at 85,2279.95 h40
  text "3" at 306.73,2276.99 h50
  text "46" at 2456.94,2276.99 h50
  text "PB12" at 2740,2179.41 h36
  text "PC3" at 85,2176.26 h46
  text "4" at 307.98,2175 h50
  text "45" at 2456.94,2175.26 h50
  text "PB11" at 2740,2084.92 h36
  text "PC4" at 85,2081.78 h46
  text "5" at 307.01,2080.98 h50
  text "44" at 2456.94,2080.51 h50
  text "PB10" at 2740,1985.11 h36
  text "PC5" at 85,1981.78 h46
  text "6" at 306.96,1980.71 h50
  text "43" at 2456.94,1980.71 h50
  text "VSS" at 85,1883.68 h40
  text "PB9" at 2737,1881.98 h46
  text "7" at 306.5,1880.71 h50
  text "42" at 2456.94,1880.45 h50
  text "PC6" at 85,1781.05 h46
  text "PB8" at 2737,1781.26 h46
  text "8" at 306.87,1779.99 h50
  text "41" at 2456.94,1779.72 h50
  text "PC7" at 85,1676.05 h46
  text "PB7" at 2737,1676.07 h46
  text "9" at 306.82,1674.99 h50
  text "40" at 2456.94,1674.99 h50
  text "PC8" at 85,1579.05 h46
  text "PB6" at 2737,1579.26 h46
  text "10" at 328.54,1577.99 h50
  text "39" at 2456.94,1577.99 h50
  text "PB5" at 2737,1476.59 h46
  text "PC9" at 85,1476.33 h46
  text "11" at 322.44,1475 h50
  text "38" at 2456.94,1475.27 h50
  text "PC10" at 85,1384.23 h40
  text "PB4" at 2737,1382.35 h46
  text "12" at 328.31,1381 h50
  text "37" at 2456.94,1381.27 h50
  text "PC11" at 85,1279.95 h40
  text "PB3" at 2737,1278.26 h46
  text "13" at 328.63,1276.99 h50
  text "36" at 2456.94,1276.99 h50
  text "PC12" at 85,1181.23 h40
  text "PB2" at 2737,1179.29 h46
  text "14" at 328.49,1178 h50
  text "35" at 2456.94,1178.27 h50
  text "PC13" at 85,1077.95 h40
  text "PB1" at 2737,1076.01 h46
  text "15" at 328.86,1074.99 h50
  text "34" at 2456.94,1074.99 h50
  text "VDD" at 85,981.96 h40
  text "PB0" at 2737,980.26 h46
  text "16" at 328.63,978.99 h50
  text "33" at 2456.94,978.99 h50
  text "PA15" at 2740,885.67 h36
  text "PA0" at 85,884.4 h40
  text "17" at 328.63,881 h50
  text "32" at 2456.94,881.27 h50
  text "PA14" at 2740,783.2 h36
  text "PA1" at 85,780.01 h46
  text "18" at 328.67,778.99 h50
  text "31" at 2456.94,778.99 h50
  text "PA13" at 2740,689.39 h36
  text "PA2" at 85,686.01 h46
  text "19" at 328.67,684.99 h50
  text "30" at 2456.94,684.99 h50
  text "PA12" at 2740,586.2 h36
  text "PA3" at 85,583.26 h46
  text "20" at 332.12,581.99 h50
  text "29" at 2456.99,581.99 h50
  text "PA11" at 2740,481.48 h36
  text "PA4" at 85,478.35 h46
  text "21" at 326.03,477 h50
  text "28" at 2456.99,477.27 h50
  text "PA10" at 2740,380.67 h36
  text "PA5" at 85,377.59 h46
  text "22" at 331.89,376 h50
  text "27" at 2456.99,376 h50
  text "23" at 332.22,283.99 h50
  text "PA6" at 85,281.98 h46
  text "PA9" at 2737,281.98 h46
  text "26" at 2456.99,269.99 h50
  text "24" at 332.08,183 h50
  text "25" at 2456.99,183.27 h50
  text "PA7" at 85,181.79 h46
  text "PA8" at 2737,181.98 h46
Mechanical 1:
  circle w5: c2320.69,2557.43 r64.72
  circle w5: c131.69,2838.43 r64.72
  circle w5: c2320.69,2092.43 r64.72
  circle w5: c420.69,2142.43 r64.72
  circle w5: c1720.69,92.43 r64.72
  circle w5: c1720.69,92.43 r64.72
  lines w5: -5.68,153.05 ccw(c73.06,153.05) 73.06,74.31 447.07,74.31 527.39,-6 1240.4,-6 1260.4,14 1310,14 1310,38 1343,38 1464,38 ; -5.69,154 -5.69,2899.31 ; -5.69,2894.94 cw(c73.06,2894.94) 73.06,2973.69 550.79,2973.69 ; 73.22,3046.15 550.95,3046.15 cw(c550.95,3028) 569.1,3028 569.1,2992 cw(c550.95,2992) 550.95,2973.85 ; 73.35,3046.15 cw(c73.35,3124.89) -5.39,3124.89 -5.39,3401.48 cw(c73.35,3401.48) 73.35,3480.22 134.78,3480.22 135,3480 135,3420 495,3420 495,3479.12 2671.95,3479.12 cw(c2671.95,3400.93) 2750.14,3400.93 2750.14,3124.34 cw(c2671.95,3124.34) 2671.95,3046.15 2133.15,3046.15 ccw(c2133.15,3028) 2115,3028 2115,2992 ccw(c2133.15,2992) 2133.15,2973.85 2671.95,2973.85 ; 1344,38 1464,38 ; 1497,13.73 1497,38 1464,38 ; 1497.36,13.73 1546.96,13.73 1566.96,-6.27 ; 1566.96,-6 1823.45,-6 ; 1825.02,-4.43 1868.45,39 ; 1888.45,59 1823.45,-6 ; 2672.03,2973.77 cw(c2672.03,2895.58) 2750.22,2895.58 2750.22,153.05 cw(c2671.48,153.06) 2671.48,74.31 1903.76,74.31 1823.45,-6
